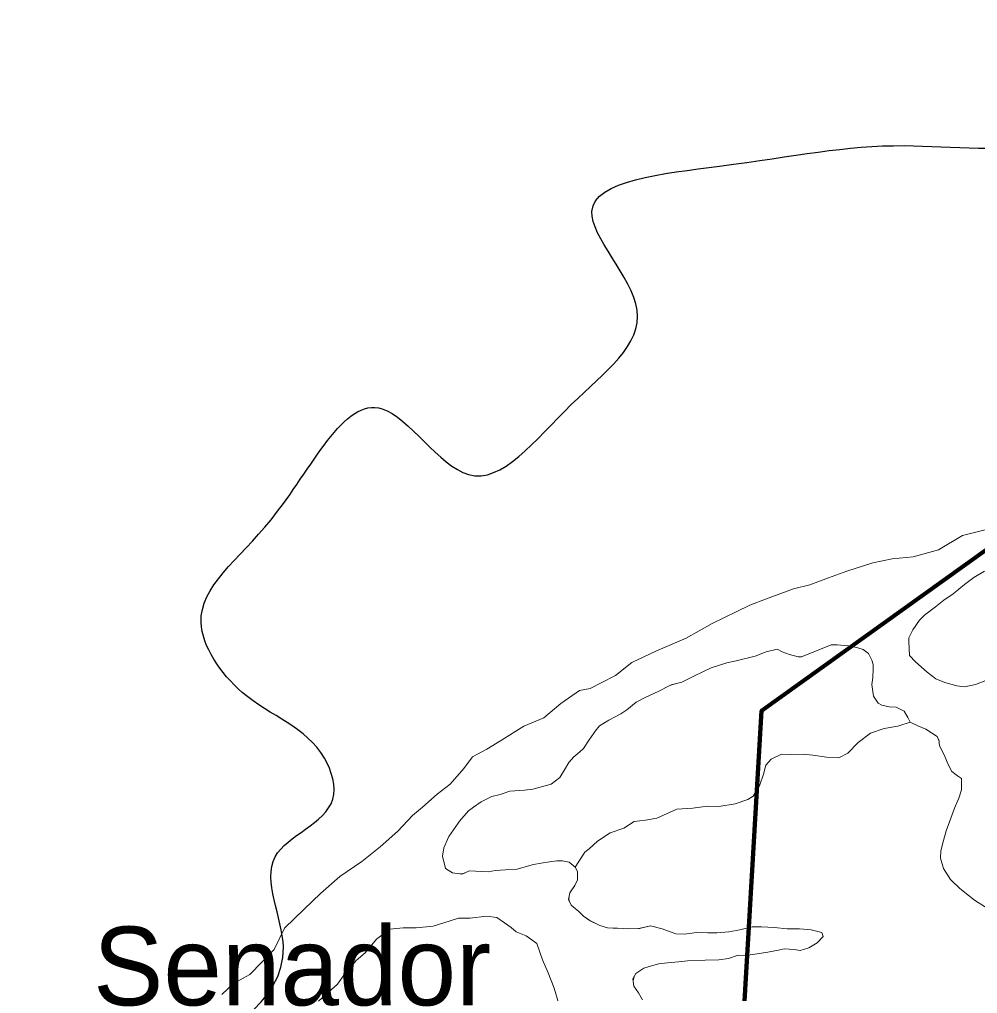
# Model space of a CAD drawing. Extents: x 553962 to 842807, y 8883888 to 9032388.
# Drawn here: x 669542 to 675627, y 8955492 to 8961682 of the extents above; entities that cross this region are included whole.
import ezdxf

# ---------------------------------------------------------------- set-up
doc = ezdxf.new("R2010")
doc.units = 0
doc.header["$LTSCALE"] = 160
for name, color, linetype, lineweight in [('21', 7, 'Continuous', 25), ('27', 7, 'Continuous', 90), ('4', 7, 'Continuous', 13)]:
    doc.layers.add(name, color=color, linetype=linetype, lineweight=lineweight)
doc.layers.add('29', color=7, linetype='Continuous')

msp = doc.modelspace()

# ---------------------------------------------------------------- linework, layer by layer
at = {"layer": '21'}
msp.add_spline([(665209.5, 8949437.1), (665261.8, 8949907.3), (665888.8, 8950560.5), (666750.9, 8951187.5), (667665.3, 8951814.5), (668344.5, 8952363.1), (668788.7, 8952911.7), (669180.6, 8953564.9), (669154.4, 8954270.2), (669755.3, 8954662.1), (670486.8, 8955027.9), (671218.3, 8955785.5), (671166.1, 8956360.3), (671531.8, 8956726), (671479.6, 8956987.3), (670957.1, 8957405.3), (670695.8, 8957849.4), (671139.9, 8958502.5), (671845.3, 8959207.9), (672394, 8958789.9), (673047.1, 8959234), (673465.1, 8959834.9), (673177.7, 8960461.9), (673987.6, 8960749.3), (675163.2, 8960879.9), (676103.7, 8960906.1), (677253.2, 8961428.6), (677697.4, 8961559.2), (678115.4, 8962133.9), (678611.8, 8962369.1), (678820.8, 8962919.9), (679291, 8963704.1), (679918, 8964226.8), (679944.1, 8964697.3), (679709, 8965272.3), (679291, 8966004.2), (678115.4, 8966945.2)], degree=3, dxfattribs=at)
at = {"layer": '27'}
msp.add_lwpolyline([(675245, 8966459.9), (679425.4, 8960995.9), (674256, 8957288.3), (673931.9, 8951754.5)], dxfattribs=at)
msp.add_spline([(637260.6, 8972975.8), (641524.5, 8971056.2), (652526.1, 8965412.7), (653164.3, 8965062.8), (670790.5, 8953770.1), (686194, 8943929.9), (696283.3, 8937647.1)], degree=3, dxfattribs=at)
at = {"layer": '4'}
for points in [[(675701.8, 8958445.7), (675532.3, 8958402.2), (675379.8, 8958311.2), (675219.3, 8958267.7), (675084.3, 8958254.7), (674962.8, 8958228.7), (674797.3, 8958176.7), (674680.3, 8958133.2), (674562.8, 8958089.7), (674458.3, 8958063.7), (674280.3, 8957998.2), (674180.3, 8957959.2), (674097.8, 8957920.2), (673941.3, 8957842.2), (673775.8, 8957750.7), (673584.8, 8957668.2), (673432.3, 8957594.7), (673328.3, 8957512.2), (673237.3, 8957465.7), (673167.8, 8957430.7), (673098.3, 8957417.7), (672980.8, 8957335.2), (672872.3, 8957244.2)], [(675690.6, 8957484.5), (675614.7, 8957455.9), (675543.8, 8957441.3), (675495.5, 8957446), (675419.2, 8957468.2), (675363.2, 8957490.5), (675308.3, 8957533.2), (675234.2, 8957598.5), (675194.5, 8957640.1), (675189.9, 8957728.8), (675189.9, 8957752.3), (675217.1, 8957803.3), (675258.6, 8957865.3), (675290.2, 8957895.9), (675360.5, 8957949.2), (675414, 8957990.5), (675472.5, 8958031.6), (675544.4, 8958091.2), (675603, 8958134.8), (675671.7, 8958175.5)], [(675671.7, 8958175.5), (675603, 8958134.8), (675544.4, 8958091.2), (675472.5, 8958031.6), (675414, 8957990.5), (675360.5, 8957949.2), (675290.2, 8957895.9), (675258.6, 8957865.3), (675217.1, 8957803.3), (675189.9, 8957752.3), (675189.9, 8957728.8), (675194.5, 8957640.1), (675234.2, 8957598.5), (675308.3, 8957533.2), (675363.2, 8957490.5), (675419.2, 8957468.2), (675495.5, 8957446), (675543.8, 8957441.3), (675614.7, 8957455.9), (675690.6, 8957484.5)], [(673818.5, 8956670.2), (673912.8, 8956682.1), (673983.8, 8956680.9), (674087.1, 8956696.3), (674168.1, 8956725.1), (674201.8, 8956746.8), (674243.7, 8956818.9), (674267.6, 8956885.3), (674283.6, 8956943.1), (674316.6, 8956981.2), (674381.2, 8957013.2), (674442, 8957011.1), (674519.4, 8957012.2), (674581.4, 8957007.4), (674667.2, 8956994.3), (674745.7, 8956989), (674803.8, 8957018.6), (674868.4, 8957086.1), (674946.6, 8957146.8), (675033.9, 8957176.7), (675122, 8957191.4), (675200.3, 8957216.5), (675184.8, 8957245), (675160.9, 8957286.4), (675111, 8957311), (675065.4, 8957313.9), (675018.8, 8957323.2), (674996.4, 8957336.6), (674966.3, 8957382.1), (674956.2, 8957456), (674961.6, 8957499), (674963.5, 8957554.7), (674964.5, 8957582.6), (674956.6, 8957610.8), (674934, 8957652.2), (674901.9, 8957677.4), (674866.7, 8957687.5), (674807.6, 8957701), (674735.5, 8957707.4), (674697.4, 8957707.4), (674620.2, 8957675.9), (674509.5, 8957630.3), (674487.9, 8957631.1), (674433.9, 8957645.7), (674386.3, 8957663.8), (674353.9, 8957680.2), (674284.8, 8957663.6), (674214.1, 8957635.7), (674093.8, 8957606.9), (674035, 8957593.8), (673936.1, 8957560.4), (673829, 8957509.7), (673749, 8957470.6), (673682.7, 8957454.3), (673681.2, 8957453.6), (673681.1, 8957451.4), (673677.3, 8957451.6), (673598.5, 8957411.2), (673519.8, 8957374.7), (673459.1, 8957342.5), (673399, 8957293.9), (673362.6, 8957269.8), (673285.1, 8957229.4), (673226.7, 8957192.1), (673198.9, 8957158.9), (673190.8, 8957146.5), (673161.4, 8957104.4), (673125.2, 8957049.8), (673101.6, 8957026.6), (673063.7, 8956994.9), (673031.8, 8956960.2), (673004.4, 8956913.7), (672973.9, 8956863.8), (672919.2, 8956821.3), (672803.6, 8956790.9), (672748.9, 8956784.8), (672657.7, 8956778.3), (672594.8, 8956756.4), (672542.3, 8956743), (672473.9, 8956709.9), (672425.8, 8956676.1), (672393.2, 8956651.9), (672337.7, 8956587.8), (672328.3, 8956574.2), (672268.2, 8956488.8), (672237.8, 8956417.6), (672228.3, 8956364.6), (672247.1, 8956285.3), (672291.8, 8956258.4), (672339.8, 8956251.6), (672364, 8956254.6), (672398.9, 8956272.3), (672519.1, 8956265.6), (672566.3, 8956272.8), (672630, 8956278.2), (672702.4, 8956282), (672754.9, 8956296.6), (672806.2, 8956312.6), (672854.7, 8956319.7), (672908.3, 8956328), (672955.5, 8956335.2)], [(673031.8, 8956960.2), (673063.7, 8956994.9), (673101.6, 8957026.6), (673125.2, 8957049.8), (673161.4, 8957104.4), (673190.8, 8957146.5), (673198.9, 8957158.9), (673226.7, 8957192.1), (673285.1, 8957229.4), (673362.6, 8957269.8), (673399, 8957293.9), (673459.1, 8957342.5), (673519.8, 8957374.7), (673598.5, 8957411.2), (673681.2, 8957453.6), (673681.2, 8957454), (673749, 8957470.6), (673829, 8957509.7), (673936.1, 8957560.4), (674035, 8957593.8), (674093.8, 8957606.9), (674214.1, 8957635.7), (674284.8, 8957663.6), (674353.9, 8957680.2), (674386.3, 8957663.8), (674433.9, 8957645.7), (674487.9, 8957631.1), (674509.5, 8957630.3), (674620.2, 8957675.9), (674697.4, 8957707.4), (674735.5, 8957707.4), (674807.6, 8957701), (674866.7, 8957687.5), (674901.9, 8957677.4), (674934, 8957652.2), (674956.6, 8957610.8), (674964.5, 8957582.6), (674963.5, 8957554.7), (674961.6, 8957499), (674956.2, 8957456), (674966.3, 8957382.1), (674996.4, 8957336.6), (675018.8, 8957323.2), (675065.4, 8957313.9), (675111, 8957311), (675160.9, 8957286.4), (675184.8, 8957245), (675200.3, 8957216.5), (675248.9, 8957193.3), (675298.9, 8957171.2), (675370.9, 8957125.5), (675383.8, 8957095.6), (675383.2, 8957078.2), (675387.7, 8957062.8), (675422.1, 8956994.3), (675439.6, 8956950.6), (675463.2, 8956902.8), (675499.1, 8956874.9), (675526.3, 8956857.5), (675525.1, 8956785.2), (675508, 8956733.8), (675481.7, 8956670), (675449.5, 8956583.6), (675427.1, 8956524.8), (675411, 8956464.4), (675393.5, 8956399.1), (675391.8, 8956350.9), (675411.1, 8956286.8), (675455.5, 8956215.5), (675515.8, 8956160.1), (675607, 8956084.6), (675693.8, 8956029.5)], [(672872.3, 8957244.2), (672746.3, 8957191.7), (672602.8, 8957100.7), (672511.3, 8957044.2), (672420.3, 8956996.2), (672363.8, 8956922.7), (672276.8, 8956822.7), (672194.3, 8956757.7), (672102.8, 8956675.2), (672037.8, 8956622.7), (671946.3, 8956523.2), (671833.3, 8956423.2), (671715.8, 8956331.7), (671576.8, 8956236.2), (671454.8, 8956127.7), (671350.8, 8956027.7), (671224.8, 8955906.2), (671159.3, 8955771.7), (671004.8, 8955611.7), (670900.8, 8955555.2), (670826.8, 8955485.7)], [(675693.8, 8956029.5), (675607, 8956084.6), (675515.8, 8956160.1), (675455.5, 8956215.5), (675411.1, 8956286.8), (675391.8, 8956350.9), (675393.5, 8956399.1), (675411, 8956464.4), (675427.1, 8956524.8), (675449.5, 8956583.6), (675481.7, 8956670), (675508, 8956733.8), (675525.1, 8956785.2), (675526.3, 8956857.5), (675499.1, 8956874.9), (675463.2, 8956902.8), (675439.6, 8956950.6), (675422.1, 8956994.3), (675387.7, 8957062.8), (675383.2, 8957078.2), (675383.6, 8957089.6), (675381.4, 8957101.1), (675370.9, 8957125.5), (675298.9, 8957171.2), (675248.9, 8957193.3), (675200.3, 8957216.5), (675122, 8957191.4), (675033.9, 8957176.7), (674946.6, 8957146.8), (674868.4, 8957086.1), (674803.8, 8957018.6), (674745.7, 8956989), (674667.2, 8956994.3), (674581.4, 8957007.4), (674519.4, 8957012.2), (674442, 8957011.1), (674381.2, 8957013.2), (674316.6, 8956981.2), (674283.6, 8956943.1), (674267.6, 8956885.3), (674243.7, 8956818.9), (674201.8, 8956746.8), (674168.1, 8956725.1), (674087.1, 8956696.3), (673983.8, 8956680.9), (673912.8, 8956682.1), (673818.5, 8956670.2), (673718, 8956662.3), (673590.4, 8956605.9), (673518.9, 8956593.2), (673446.4, 8956585.6), (673380.2, 8956543.5), (673292.9, 8956513.6), (673213.6, 8956460.6), (673161.1, 8956411.7), (673132.5, 8956389.9), (673070.8, 8956295.6), (673086.3, 8956267.2), (673087, 8956215.1), (673069.2, 8956177.7), (673043.8, 8956141.8), (673035.5, 8956123.1), (673030.7, 8956094.1), (673035.2, 8956077.4), (673045.8, 8956054.2), (673071.7, 8956031.7), (673095.1, 8956011.9), (673124.5, 8955982.9), (673159.2, 8955958.9), (673181.6, 8955946.7), (673229, 8955924.7), (673277.9, 8955909), (673313.4, 8955907.8), (673340, 8955906.8), (673412.1, 8955901.8), (673471.9, 8955904.7), (673496.1, 8955909), (673549.9, 8955922.3), (673624, 8955901.9), (673710.5, 8955871), (673764.9, 8955869), (673845.2, 8955878.9), (673913.6, 8955876.5), (673970.8, 8955878.3), (674047.1, 8955883.2), (674117.3, 8955896)], [(673500.3, 8955450.8), (673474, 8955496.2), (673445, 8955539), (673437.7, 8955585.8), (673456.7, 8955618.6), (673508.7, 8955652.2), (673557.4, 8955667), (673603.5, 8955680.6), (673658.3, 8955687.6), (673727.1, 8955694), (673785.6, 8955699.6), (673897.4, 8955703.3), (673983.7, 8955705.3), (674044.9, 8955714.6), (674106.6, 8955735.2), (674153.4, 8955733.6), (674227.4, 8955744.9), (674295, 8955755.2), (674362.7, 8955766.8), (674398.5, 8955775.7), (674461.8, 8955770.9), (674500.9, 8955764.5), (674554.8, 8955781.6), (674609.2, 8955813.9), (674646.1, 8955853.2), (674638.1, 8955878.9), (674570.2, 8955896.5), (674495.6, 8955902.9), (674418.2, 8955901.9), (674336, 8955911.1), (674255, 8955916.5), (674196.6, 8955914.7), (674117.3, 8955896), (674047.1, 8955883.2), (673970.8, 8955878.3), (673913.6, 8955876.5), (673845.2, 8955878.9), (673764.9, 8955869), (673710.5, 8955871), (673624, 8955901.9), (673549.9, 8955922.3), (673480.9, 8955905.2), (673412.1, 8955901.8), (673340, 8955906.8), (673313.4, 8955907.8), (673277.9, 8955909), (673229, 8955924.7), (673167.1, 8955953.4), (673124.5, 8955982.9), (673095.1, 8956011.9), (673071.7, 8956031.7), (673045.8, 8956054.2), (673029.9, 8956089.1), (673037.1, 8956132.3), (673069.2, 8956177.7), (673087, 8956215.1), (673086.3, 8956267.2), (673070.8, 8956295.6), (673032.6, 8956327.4), (672992.2, 8956333.9), (672955.5, 8956335.2), (672908.3, 8956328), (672854.7, 8956319.7), (672806.2, 8956312.6), (672754.9, 8956296.6), (672702.4, 8956282), (672630, 8956278.2), (672566.3, 8956272.8), (672519.1, 8956265.6), (672398.9, 8956272.3), (672354.2, 8956249.6), (672291.8, 8956258.4), (672247.1, 8956285.3), (672228.3, 8956364.6), (672237.8, 8956417.6), (672268.2, 8956488.8), (672328.3, 8956574.2), (672337.7, 8956587.8), (672393.2, 8956651.9), (672425.8, 8956676.1), (672473.9, 8956709.9), (672542.3, 8956743), (672594.8, 8956756.4), (672657.7, 8956778.3), (672748.9, 8956784.8), (672803.6, 8956790.9), (672919.2, 8956821.3), (672973.9, 8956863.8), (673004.4, 8956913.7), (673031.8, 8956960.2)], [(672955.5, 8956335.2), (672992.2, 8956333.9), (673032.6, 8956327.4), (673070.8, 8956295.6), (673132.5, 8956389.9), (673161.1, 8956411.7), (673213.6, 8956460.6), (673292.9, 8956513.6), (673380.2, 8956543.5), (673446.4, 8956585.6), (673518.9, 8956593.2), (673590.4, 8956605.9), (673718, 8956662.3), (673818.5, 8956670.2)], [(672966.8, 8955432.8), (672938.4, 8955526.4), (672900, 8955624.2), (672864.8, 8955706.6), (672829.1, 8955809.4), (672759.9, 8955857.9), (672697.2, 8955884.3), (672664.2, 8955910.7), (672622.4, 8955941.4), (672574, 8955975.5), (672508.8, 8955982.9), (672405.5, 8955970.1), (672329.7, 8955970.8), (672236.9, 8955940.8), (672170.1, 8955920.7), (672060.7, 8955909.3), (671980.1, 8955909.9), (671894.2, 8955901.7), (671810.5, 8955837.7), (671738.6, 8955750.1), (671680.5, 8955701.3), (671642.4, 8955654.3), (671607.8, 8955617.2), (671561.7, 8955550.6), (671503, 8955497.4), (671441.8, 8955443.9)], [(671441.8, 8955443.9), (671503, 8955497.4), (671561.7, 8955550.6), (671607.8, 8955617.2), (671642.4, 8955654.3), (671680.5, 8955701.3), (671738.6, 8955750.1), (671810.5, 8955837.7), (671894.2, 8955901.7), (671980.1, 8955909.9), (672060.7, 8955909.3), (672170.1, 8955920.7), (672236.9, 8955940.8), (672329.7, 8955970.8), (672405.5, 8955970.1), (672508.8, 8955982.9), (672574, 8955975.5), (672622.4, 8955941.4), (672664.2, 8955910.7), (672697.2, 8955884.3), (672759.9, 8955857.9), (672829.1, 8955809.4), (672864.8, 8955706.6), (672900, 8955624.2), (672938.4, 8955526.4), (672966.8, 8955432.8)], [(674117.3, 8955896), (674196.6, 8955914.7), (674255, 8955916.5), (674336, 8955911.1), (674418.2, 8955901.9), (674495.6, 8955902.9), (674570.2, 8955896.5), (674638.1, 8955878.9), (674646.1, 8955853.2), (674609.2, 8955813.9), (674554.8, 8955781.6), (674500.9, 8955764.5), (674461.8, 8955770.9), (674398.5, 8955775.7), (674362.7, 8955766.8), (674295, 8955755.2), (674227.4, 8955744.9), (674153.4, 8955733.6), (674106.6, 8955735.2), (674044.9, 8955714.6), (673983.7, 8955705.3), (673897.4, 8955703.3), (673785.6, 8955699.6), (673727.1, 8955694), (673658.3, 8955687.6), (673603.5, 8955680.6), (673557.4, 8955667), (673508.7, 8955652.2), (673456.7, 8955618.6), (673445.9, 8955599.9), (673439.9, 8955572.2), (673445, 8955539), (673474, 8955496.2), (673500.3, 8955450.8)]]:
    msp.add_lwpolyline(points, dxfattribs=at)

# ---------------------------------------------------------------- texts
at = {"layer": '29'}
msp.add_text('Senador', height=500, dxfattribs=at).set_placement((670009.9, 8955416.6))

doc.saveas('drawing.dxf')
